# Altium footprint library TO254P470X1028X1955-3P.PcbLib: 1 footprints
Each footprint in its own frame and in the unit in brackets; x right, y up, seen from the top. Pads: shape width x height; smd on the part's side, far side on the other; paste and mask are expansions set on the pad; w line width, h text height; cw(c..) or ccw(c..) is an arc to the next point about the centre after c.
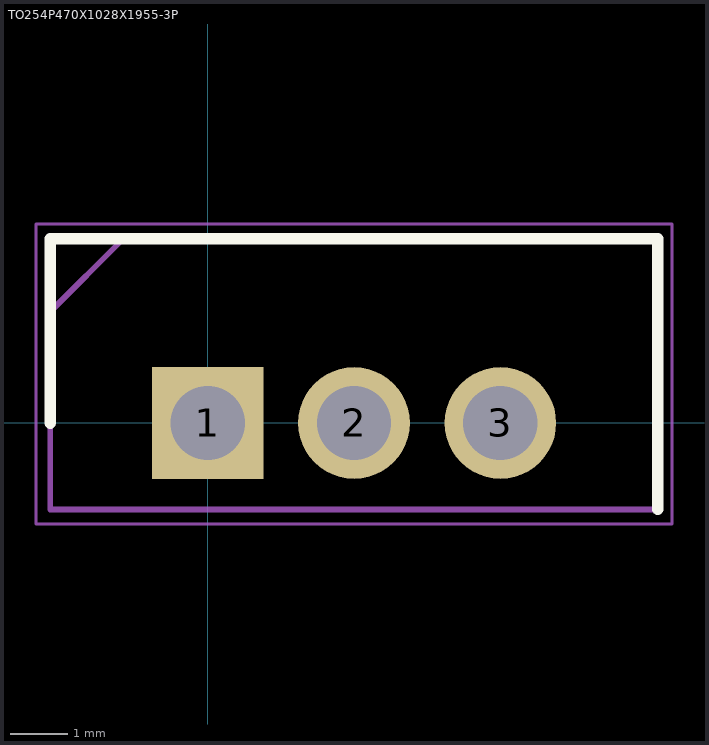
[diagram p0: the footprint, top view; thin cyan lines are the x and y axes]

## TO254P470X1028X1955-3P [mm]
pads (3):
  rect 1.935x1.935 / inner round 1.935 / far side rect 1.935x1.935 hole 1.29: 1(0,0)
  round 1.935 hole 1.29: 2(2.54,0) 3(5.08,0)
Top Overlay:
  lines w0.2: -2.73,0 -2.73,3.2 7.81,3.2 7.81,-1.5
Mechanical 15:
  lines w0.1: -2.73,1.93 -1.46,3.2 ; -2.73,-1.5 7.81,-1.5 7.81,3.2 -2.73,3.2 -2.73,-1.5
Mechanical 20:
  lines w0.05: -2.98,-1.75 8.06,-1.75 8.06,3.45 -2.98,3.45 -2.98,-1.75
